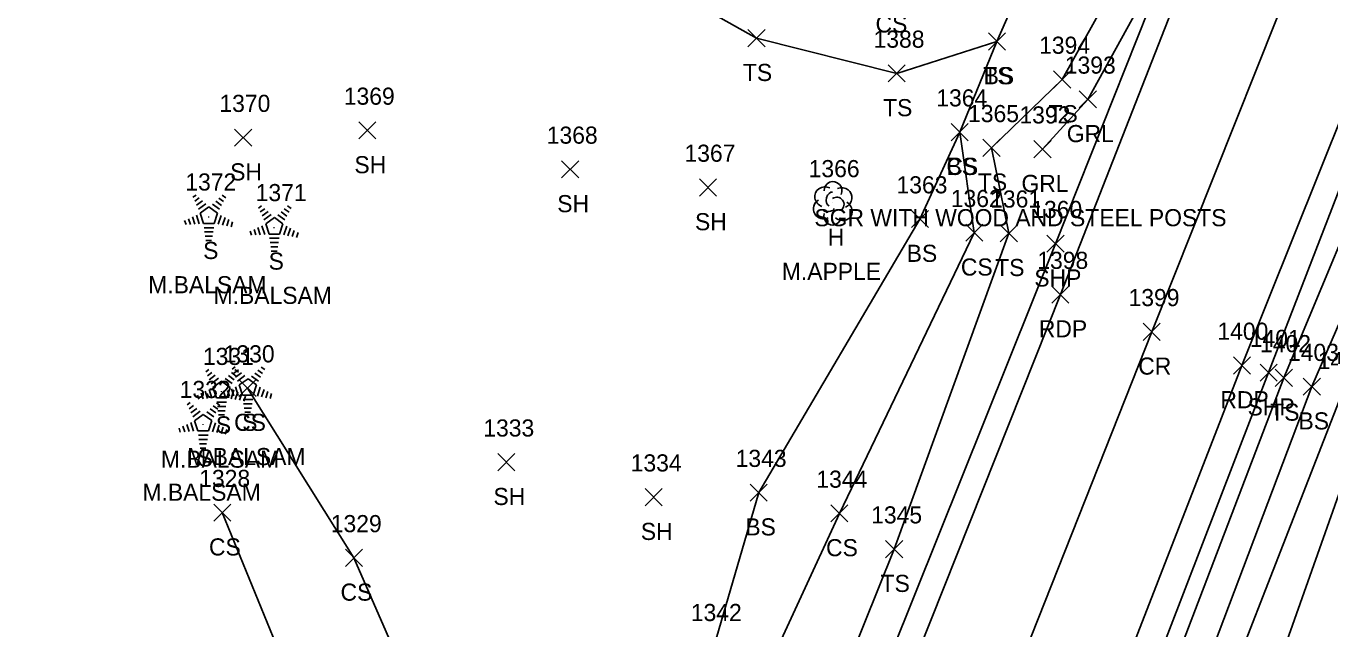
# Model space of a CAD drawing. Extents: x 1554917 to 1555870, y 813367 to 816333.
# Drawn here: x 1555040.5 to 1555192.9, y 813861.5 to 813931.9 of the extents above; entities that cross this region are included whole.
import ezdxf

# ---------------------------------------------------------------- set-up
doc = ezdxf.new("R2010")
doc.units = 0
for name, color, linetype in [('L_A', 7, 'Continuous'), ('L_C', 7, 'Continuous'), ('L_I', 7, 'Continuous'), ('L_TIC', 7, 'Continuous'), ('LELB', 7, 'Continuous'), ('LTC', 7, 'Continuous'), ('LTD', 7, 'Continuous'), ('P_A', 7, 'Continuous'), ('P_I', 7, 'Continuous'), ('P_TIC', 7, 'Continuous'), ('PET', 7, 'Continuous'), ('PRC', 7, 'Continuous'), ('PSP', 7, 'Continuous'), ('R_A', 7, 'Continuous'), ('R_C', 7, 'Continuous'), ('R_I', 7, 'Continuous'), ('R_TIC', 7, 'Continuous'), ('RGR', 7, 'Continuous')]:
    doc.layers.add(name, color=color, linetype=linetype)

msp = doc.modelspace()

# ---------------------------------------------------------------- linework, layer by layer
at = {"layer": 'L_TIC'}
for points in [[(1555124.87, 813929.47), (1555126.87, 813931.47)], [(1555126.87, 813929.47), (1555124.87, 813931.47)], [(1555152.95, 813929.09), (1555154.95, 813931.09)], [(1555154.95, 813929.09), (1555152.95, 813931.09)], [(1555152.95, 813929.09), (1555154.95, 813931.09)], [(1555154.95, 813929.09), (1555152.95, 813931.09)], [(1555141.24, 813925.36), (1555143.24, 813927.36)], [(1555143.24, 813925.36), (1555141.24, 813927.36)], [(1555160.57, 813924.65), (1555162.57, 813926.65)], [(1555162.57, 813924.65), (1555160.57, 813926.65)], [(1555064.9, 813917.86), (1555066.9, 813919.86)], [(1555066.9, 813917.86), (1555064.9, 813919.86)], [(1555079.4, 813918.7), (1555081.4, 813920.7)], [(1555081.4, 813918.7), (1555079.4, 813920.7)], [(1555148.61, 813918.5), (1555150.61, 813920.5)], [(1555150.61, 813918.5), (1555148.61, 813920.5)], [(1555148.61, 813918.5), (1555150.61, 813920.5)], [(1555150.61, 813918.5), (1555148.61, 813920.5)], [(1555152.32, 813916.67), (1555154.32, 813918.67)], [(1555154.32, 813916.67), (1555152.32, 813918.67)], [(1555103.1, 813914.15), (1555105.1, 813916.15)], [(1555105.1, 813914.15), (1555103.1, 813916.15)], [(1555119.19, 813912.04), (1555121.19, 813914.04)], [(1555121.19, 813912.04), (1555119.19, 813914.04)], [(1555143.96, 813908.35), (1555145.96, 813910.35)], [(1555145.96, 813908.35), (1555143.96, 813910.35)], [(1555150.3, 813906.75), (1555152.3, 813908.75)], [(1555152.3, 813906.75), (1555150.3, 813908.75)], [(1555154.34, 813906.69), (1555156.34, 813908.69)], [(1555156.34, 813906.69), (1555154.34, 813908.69)], [(1555186.47, 813889.8), (1555188.47, 813891.8)], [(1555188.47, 813889.8), (1555186.47, 813891.8)], [(1555065.4, 813888.61), (1555067.4, 813890.61)], [(1555067.4, 813888.61), (1555065.4, 813890.61)], [(1555189.74, 813888.78), (1555191.74, 813890.78)], [(1555191.74, 813888.78), (1555189.74, 813890.78)], [(1555095.64, 813879.95), (1555097.64, 813881.95)], [(1555097.64, 813879.95), (1555095.64, 813881.95)], [(1555112.86, 813875.87), (1555114.86, 813877.87)], [(1555114.86, 813875.87), (1555112.86, 813877.87)], [(1555125.12, 813876.4), (1555127.12, 813878.4)], [(1555127.12, 813876.4), (1555125.12, 813878.4)], [(1555062.46, 813874.06), (1555064.46, 813876.06)], [(1555064.46, 813874.06), (1555062.46, 813876.06)], [(1555134.55, 813873.97), (1555136.55, 813875.97)], [(1555136.55, 813873.97), (1555134.55, 813875.97)], [(1555140.95, 813869.8), (1555142.95, 813871.8)], [(1555142.95, 813869.8), (1555140.95, 813871.8)], [(1555077.83, 813868.78), (1555079.83, 813870.78)], [(1555079.83, 813868.78), (1555077.83, 813870.78)]]:
    msp.add_lwpolyline(points, dxfattribs=at)
at = {"layer": 'LELB'}
for points in [[(1555078.74, 813957.64), (1555092.79, 813950.17), (1555112.4, 813938.05), (1555125.87, 813930.47), (1555142.24, 813926.36), (1555153.95, 813930.09)], [(1555019.54, 813585.69), (1555024.77, 813597.99), (1555042.65, 813620.9), (1555048.58, 813631.85), (1555066.52, 813674.6), (1555093.66, 813750.68), (1555103.98, 813778.92), (1555100.94, 813788.26), (1555095.86, 813797.4), (1555100.34, 813804.26), (1555113.07, 813834.65), (1555120.88, 813859.4), (1555126.12, 813877.4), (1555144.96, 813909.35), (1555149.61, 813919.5), (1555153.95, 813930.09), (1555158.29, 813940)], [(1554960.86, 813387.22), (1554975.88, 813430.61), (1554997.67, 813492.71), (1555013.89, 813538.05), (1555028.68, 813579.18), (1555048.82, 813626.54), (1555068.18, 813674.18), (1555096.05, 813749.22), (1555111.01, 813785.1), (1555115.51, 813798.83), (1555119.3, 813812.87), (1555134.87, 813853.17), (1555141.95, 813870.8), (1555155.34, 813907.69), (1555153.32, 813917.67), (1555161.57, 813925.65), (1555168.92, 813938.89)], [(1555091.02, 813589.64), (1555093.93, 813609.08), (1555110.01, 813657.36), (1555123.68, 813699.33), (1555136.3, 813730.66), (1555163.02, 813794.74), (1555179.29, 813835.95), (1555197.25, 813886.69), (1555209.44, 813915.13), (1555210.66, 813920.37)], [(1554992.4, 813377.01), (1555009.62, 813423.34), (1555030.72, 813482.86), (1555047.7, 813528.1), (1555056, 813550.42), (1555062.05, 813566.99), (1555080.33, 813615.57), (1555099.41, 813662.25), (1555114.13, 813700.62), (1555127, 813733.84), (1555152.94, 813799.24), (1555168.16, 813840.25), (1555187.47, 813890.8), (1555199.5, 813919.6)], [(1555111.01, 813785.1), (1555105.42, 813789.67), (1555105.04, 813797.66), (1555119.58, 813831.83), (1555126.62, 813855.57), (1555135.55, 813874.97), (1555151.3, 813907.75), (1555149.61, 813919.5)], [(1554997.34, 813375.96), (1555001.03, 813380.2), (1555008.26, 813399.3), (1555016.85, 813422.36), (1555039.01, 813478.41), (1555055.21, 813525.71), (1555062.73, 813548.53), (1555066.84, 813564.4), (1555085.89, 813613.91), (1555101.8, 813661.36), (1555117.2, 813700.9), (1555129.69, 813732.82), (1555155.55, 813797.61), (1555171.4, 813838.65), (1555190.74, 813889.78), (1555201.42, 813914.42), (1555204.39, 813917.83), (1555206.44, 813916.94)], [(1555060.32, 813524.58), (1555067.83, 813537.87), (1555070.43, 813550.96), (1555072.05, 813560.86), (1555087.88, 813613.15), (1555106.35, 813658.95), (1555120.2, 813700.04), (1555133.19, 813731.1), (1555158.65, 813797.07), (1555174.38, 813837.99), (1555194.21, 813888.82), (1555206.44, 813916.94)], [(1555091.62, 813821.03), (1555091.89, 813839.84), (1555078.83, 813869.78), (1555066.4, 813889.61)], [(1555081.71, 813836.71), (1555072.21, 813853.66), (1555063.46, 813875.06)]]:
    msp.add_lwpolyline(points, dxfattribs=at)
at = {"layer": 'LTC'}
for p, q in [((1555060.03, 813911.89), (1555060.39, 813912.15)), ((1555060.24, 813911.42), (1555060.77, 813911.81)), ((1555060.45, 813910.96), (1555061.15, 813911.47)), ((1555060.66, 813910.49), (1555061.54, 813911.13)), ((1555060.88, 813910.04), (1555061.9, 813910.77)), ((1555061.9, 813910.77), (1555062.89, 813910.05)), ((1555062.32, 813911.08), (1555063.13, 813910.5)), ((1555062.69, 813911.43), (1555063.37, 813910.94)), ((1555063.06, 813911.78), (1555063.61, 813911.38)), ((1555063.43, 813912.13), (1555063.85, 813911.83)), ((1555067.68, 813910.64), (1555068.03, 813910.9)), ((1555071.08, 813910.88), (1555071.49, 813910.58)), ((1555059.06, 813909.17), (1555059.22, 813908.7)), ((1555059.52, 813909.39), (1555059.73, 813908.73)), ((1555059.97, 813909.6), (1555060.25, 813908.77)), ((1555060.43, 813909.82), (1555060.76, 813908.8)), ((1555060.88, 813910.04), (1555061.27, 813908.84)), ((1555062.89, 813910.05), (1555062.5, 813908.84)), ((1555063.33, 813909.78), (1555062.99, 813908.74)), ((1555063.78, 813909.53), (1555063.49, 813908.64)), ((1555064.22, 813909.28), (1555063.98, 813908.55)), ((1555067.89, 813910.18), (1555068.42, 813910.56)), ((1555068.1, 813909.71), (1555068.8, 813910.22)), ((1555068.31, 813909.25), (1555069.18, 813909.88)), ((1555068.53, 813908.79), (1555069.54, 813909.53)), ((1555069.54, 813909.53), (1555070.54, 813908.8)), ((1555069.96, 813909.84), (1555070.77, 813909.25)), ((1555070.33, 813910.19), (1555071.01, 813909.69)), ((1555070.7, 813910.54), (1555071.25, 813910.14)), ((1555062.5, 813908.84), (1555061.27, 813908.84)), ((1555062.46, 813908.34), (1555061.32, 813908.34)), ((1555062.38, 813907.84), (1555061.39, 813907.84)), ((1555064.66, 813909.03), (1555064.48, 813908.45)), ((1555066.71, 813907.92), (1555066.86, 813907.46)), ((1555067.16, 813908.14), (1555067.38, 813907.49)), ((1555067.62, 813908.36), (1555067.89, 813907.52)), ((1555068.08, 813908.57), (1555068.41, 813907.55)), ((1555068.53, 813908.79), (1555068.92, 813907.6)), ((1555070.15, 813907.6), (1555068.92, 813907.6)), ((1555070.54, 813908.8), (1555070.15, 813907.6)), ((1555070.98, 813908.53), (1555070.64, 813907.49)), ((1555071.42, 813908.28), (1555071.13, 813907.4)), ((1555071.87, 813908.03), (1555071.63, 813907.3)), ((1555072.31, 813907.78), (1555072.12, 813907.21)), ((1555062.3, 813907.34), (1555061.46, 813907.34)), ((1555062.21, 813906.84), (1555061.54, 813906.84)), ((1555070.11, 813907.1), (1555068.96, 813907.1)), ((1555070.03, 813906.6), (1555069.04, 813906.6)), ((1555069.94, 813906.1), (1555069.11, 813906.1)), ((1555069.86, 813905.6), (1555069.18, 813905.6)), ((1555061.52, 813891.52), (1555061.87, 813891.78)), ((1555061.73, 813891.05), (1555062.25, 813891.44)), ((1555061.93, 813890.59), (1555062.64, 813891.1)), ((1555064.17, 813891.06), (1555064.85, 813890.57)), ((1555064.54, 813891.41), (1555065.09, 813891.01)), ((1555064.59, 813891.82), (1555064.95, 813892.08)), ((1555064.8, 813891.36), (1555065.33, 813891.74)), ((1555064.91, 813891.76), (1555065.33, 813891.45)), ((1555065.01, 813890.89), (1555065.71, 813891.4)), ((1555065.22, 813890.42), (1555066.1, 813891.06)), ((1555066.88, 813891.02), (1555067.69, 813890.43)), ((1555067.25, 813891.36), (1555067.93, 813890.87)), ((1555067.62, 813891.71), (1555068.17, 813891.31)), ((1555067.99, 813892.06), (1555068.41, 813891.76)), ((1555061.91, 813889.45), (1555062.25, 813888.43)), ((1555062.14, 813890.12), (1555063.02, 813890.76)), ((1555062.37, 813889.67), (1555063.38, 813890.4)), ((1555062.37, 813889.67), (1555062.76, 813888.47)), ((1555063.38, 813890.4), (1555064.38, 813889.68)), ((1555063.8, 813890.71), (1555064.61, 813890.13)), ((1555064.38, 813889.68), (1555063.99, 813888.47)), ((1555064.08, 813889.32), (1555064.29, 813888.66)), ((1555064.82, 813889.41), (1555064.48, 813888.37)), ((1555064.53, 813889.53), (1555064.81, 813888.7)), ((1555064.99, 813889.75), (1555065.32, 813888.73)), ((1555065.44, 813889.97), (1555066.46, 813890.7)), ((1555065.44, 813889.97), (1555065.83, 813888.78)), ((1555066.46, 813890.7), (1555067.45, 813889.98)), ((1555067.45, 813889.98), (1555067.06, 813888.78)), ((1555067.89, 813889.71), (1555067.55, 813888.67)), ((1555068.34, 813889.46), (1555068.05, 813888.57)), ((1555059.37, 813887.65), (1555059.72, 813887.91)), ((1555060.55, 813888.8), (1555060.7, 813888.33)), ((1555061, 813889.01), (1555061.22, 813888.36)), ((1555061.46, 813889.23), (1555061.73, 813888.4)), ((1555063.99, 813888.47), (1555062.76, 813888.47)), ((1555062.77, 813887.89), (1555063.18, 813887.59)), ((1555063.95, 813887.97), (1555062.8, 813887.97)), ((1555063.62, 813889.1), (1555063.78, 813888.63)), ((1555065.26, 813889.16), (1555064.97, 813888.27)), ((1555065.7, 813888.91), (1555065.47, 813888.18)), ((1555067.06, 813888.78), (1555065.83, 813888.78)), ((1555067.02, 813888.28), (1555065.88, 813888.28)), ((1555066.94, 813887.78), (1555065.95, 813887.78)), ((1555066.15, 813888.65), (1555065.96, 813888.08)), ((1555068.78, 813889.21), (1555068.54, 813888.48)), ((1555069.22, 813888.96), (1555069.04, 813888.38)), ((1555059.58, 813887.19), (1555060.11, 813887.57)), ((1555059.79, 813886.72), (1555060.49, 813887.23)), ((1555060, 813886.26), (1555060.87, 813886.9)), ((1555060.22, 813885.8), (1555061.23, 813886.54)), ((1555061.23, 813886.54), (1555062.23, 813885.81)), ((1555061.65, 813886.85), (1555062.46, 813886.26)), ((1555062.02, 813887.2), (1555062.7, 813886.7)), ((1555062.39, 813887.55), (1555062.94, 813887.15)), ((1555063.86, 813887.47), (1555062.88, 813887.47)), ((1555063.78, 813886.97), (1555062.95, 813886.97)), ((1555063.7, 813886.47), (1555063.02, 813886.47)), ((1555066.86, 813887.28), (1555066.02, 813887.28)), ((1555066.77, 813886.78), (1555066.1, 813886.78)), ((1555058.4, 813884.93), (1555058.55, 813884.47)), ((1555058.86, 813885.15), (1555059.07, 813884.5)), ((1555059.31, 813885.37), (1555059.58, 813884.53)), ((1555059.77, 813885.58), (1555060.1, 813884.56)), ((1555060.22, 813885.8), (1555060.61, 813884.61)), ((1555062.23, 813885.81), (1555061.84, 813884.61)), ((1555062.67, 813885.54), (1555062.33, 813884.5)), ((1555063.11, 813885.29), (1555062.82, 813884.41)), ((1555063.56, 813885.04), (1555063.32, 813884.31)), ((1555064, 813884.79), (1555063.81, 813884.22)), ((1555061.84, 813884.61), (1555060.61, 813884.61)), ((1555061.8, 813884.11), (1555060.66, 813884.11)), ((1555061.72, 813883.61), (1555060.73, 813883.61)), ((1555061.63, 813883.11), (1555060.8, 813883.11)), ((1555061.55, 813882.61), (1555060.87, 813882.61))]:
    msp.add_line(p, q, dxfattribs=at)
at = {"layer": 'LTD'}
msp.add_line((1555134.76, 813911.24), (1555134.76, 813911.24), dxfattribs=at)
msp.add_line((1555134.76, 813911.24), (1555134.76, 813911.24), dxfattribs=at)
msp.add_arc((1555134.8, 813912.67), 1.05, 335.5272, 180.9563, dxfattribs=at)
for centre, major_axis, ratio, start_param, end_param in [((1555133.97, 813911.9), (1.21, -0.51), 0.895232, 1.570796, 4.712389), ((1555134.55, 813911.69), (-0.208, -0.792), 0.645439, 3.141593, 6.283185), ((1555135.8, 813911.82), (-1.14, -0.48), 0.949671, 1.570796, 4.712389), ((1555133.67, 813910.53), (0.58, -1.04), 0.959034, 3.141593, 6.283185), ((1555135.26, 813911.07), (-0.5, 0.667), 0.989748, 3.141593, 6.283185), ((1555135.76, 813910.4), (-1.09, 0.79), 0.841452, 1.570796, 4.712389), ((1555134.76, 813909.74), (0.26, 1.06), 0.942809, 1.570796, 4.712389), ((1555134.3, 813910.49), (-0.625, -0.083), 0.423636, 0, 3.141593)]:
    msp.add_ellipse(centre, major_axis=major_axis, ratio=ratio, start_param=start_param, end_param=end_param, dxfattribs=at)
at = {"layer": 'P_TIC'}
for points in [[(1555159.79, 813905.47), (1555161.79, 813907.47)], [(1555161.79, 813905.47), (1555159.79, 813907.47)], [(1555160.36, 813899.53), (1555162.36, 813901.53)], [(1555162.36, 813899.53), (1555160.36, 813901.53)], [(1555171.03, 813895.18), (1555173.03, 813897.18)], [(1555173.03, 813895.18), (1555171.03, 813897.18)], [(1555181.57, 813891.25), (1555183.57, 813893.25)], [(1555183.57, 813891.25), (1555181.57, 813893.25)], [(1555184.69, 813890.41), (1555186.69, 813892.41)], [(1555186.69, 813890.41), (1555184.69, 813892.41)]]:
    msp.add_lwpolyline(points, dxfattribs=at)
at = {"layer": 'PET'}
for points in [[(1554965.43, 813385.56), (1554980.95, 813429.92), (1555003.19, 813490.59), (1555019.55, 813535.73), (1555035.2, 813576.47), (1555053.52, 813624.76), (1555072.33, 813672.52), (1555101.11, 813747.71), (1555125.53, 813809.89), (1555141.72, 813851.12), (1555161.36, 813900.53), (1555183.5, 813956.99)], [(1554987.55, 813378.28), (1555004.34, 813425.43), (1555025.15, 813482.53), (1555042.33, 813529.78), (1555057.09, 813568.35), (1555075.57, 813617.35), (1555093.79, 813663.7), (1555108.49, 813702.81), (1555121.71, 813736.27), (1555147.41, 813801.52), (1555163.02, 813841.94), (1555182.57, 813892.25), (1555203.7, 813945.01)]]:
    msp.add_lwpolyline(points, dxfattribs=at)
at = {"layer": 'PRC'}
msp.add_lwpolyline([(1554976.76, 813382.18), (1554992.84, 813427.9), (1555014.07, 813486.01), (1555030.62, 813532.31), (1555046.37, 813573.08), (1555064.69, 813621.19), (1555082.41, 813667.53), (1555112.1, 813744.1), (1555110.69, 813739.79), (1555136.16, 813805.74), (1555152.52, 813846.93), (1555172.03, 813896.18), (1555193.96, 813951.2), (1555206.37, 813983.4), (1555218.13, 814013.22), (1555228.65, 814039.26), (1555237.93, 814064.31), (1555252.22, 814099.76), (1555265.8, 814135.89), (1555275.26, 814160.09), (1555297.17, 814214.77), (1555313.83, 814257.94), (1555329.72, 814298.26), (1555342.03, 814329.92)], dxfattribs=at)
at = {"layer": 'PSP'}
for points in [[(1554990.52, 813377.71), (1555007.26, 813424.1), (1555027.97, 813481.79), (1555045.41, 813528.93), (1555059.94, 813567), (1555096.82, 813663.08), (1555111.75, 813701.59), (1555124.82, 813734.75), (1555150.26, 813800.36), (1555166.19, 813840.91), (1555185.69, 813891.41), (1555197.67, 813922.42), (1555211.91, 813956.86)], [(1554963, 813386.3), (1554978.53, 813430.4), (1555000.44, 813491.39), (1555017.18, 813537.03), (1555032.55, 813577.93), (1555050.86, 813625.69), (1555069.49, 813673.81), (1555098.21, 813748.28), (1555122.69, 813810.6), (1555138.9, 813851.92), (1555160.79, 813906.47), (1555173.05, 813937.33)]]:
    msp.add_lwpolyline(points, dxfattribs=at)
at = {"layer": 'R_TIC'}
for points in [[(1555163.57, 813922.33), (1555165.57, 813924.33)], [(1555165.57, 813922.33), (1555163.57, 813924.33)], [(1555158.27, 813916.51), (1555160.27, 813918.51)], [(1555160.27, 813916.51), (1555158.27, 813918.51)]]:
    msp.add_lwpolyline(points, dxfattribs=at)
at = {"layer": 'RGR'}
msp.add_lwpolyline([(1555159.27, 813917.51), (1555164.57, 813923.33), (1555172.45, 813937.61), (1555174.85, 813944.62), (1555176.88, 813950.76), (1555185.36, 813973.38), (1555192.77, 813990.92), (1555204.01, 814018.12), (1555214.74, 814044.68), (1555224.38, 814069.2), (1555237.86, 814103.71), (1555245.14, 814124.79), (1555246.27, 814138.04)], dxfattribs=at)

# ---------------------------------------------------------------- texts
at = {"layer": 'L_A'}
for s, p in [('CS', (1555139.77, 813931.14)), ('TS', (1555124.28, 813925.47)), ('TS', (1555152.36, 813925.09)), ('BS', (1555152.39, 813925.09)), ('TS', (1555140.65, 813921.36)), ('TS', (1555159.98, 813920.65)), ('SH', (1555078.89, 813914.7)), ('SH', (1555064.38, 813913.86)), ('CS', (1555148.05, 813914.5)), ('BS', (1555148.05, 813914.5)), ('TS', (1555151.73, 813912.67)), ('SH', (1555102.59, 813910.15)), ('SH', (1555118.68, 813908.04)), ('H', (1555134.19, 813906.24)), ('S', (1555061.22, 813904.68)), ('BS', (1555143.41, 813904.35)), ('S', (1555068.87, 813903.44)), ('CS', (1555149.74, 813902.75)), ('TS', (1555153.75, 813902.69)), ('TS', (1555185.88, 813885.8)), ('S', (1555062.71, 813884.31)), ('CS', (1555064.84, 813884.61)), ('S', (1555065.78, 813884.61)), ('BS', (1555189.18, 813884.78)), ('S', (1555060.56, 813880.45)), ('SH', (1555095.13, 813875.95)), ('BS', (1555124.56, 813872.4)), ('SH', (1555112.35, 813871.87)), ('CS', (1555061.9, 813870.06)), ('CS', (1555133.99, 813869.97)), ('CS', (1555077.27, 813864.78)), ('TS', (1555140.36, 813865.8))]:
    msp.add_text(s, height=2, dxfattribs=at).set_placement(p)
at = {"layer": 'L_C'}
for s, p in [('M.APPLE', (1555128.82, 813902.24)), ('M.BALSAM', (1555054.8, 813900.68)), ('M.BALSAM', (1555062.44, 813899.44)), ('M.BALSAM', (1555056.28, 813880.31)), ('M.BALSAM', (1555059.36, 813880.61)), ('M.BALSAM', (1555054.13, 813876.45))]:
    msp.add_text(s, height=2, dxfattribs=at).set_placement(p)
at = {"layer": 'L_I'}
for s, p in [('1388', (1555139.54, 813929.36)), ('1394', (1555158.88, 813928.65)), ('1369', (1555077.65, 813922.7)), ('1364', (1555146.87, 813922.5)), ('1364', (1555146.87, 813922.5)), ('1370', (1555063.12, 813921.86)), ('1365', (1555150.58, 813920.67)), ('1368', (1555101.36, 813918.15)), ('1367', (1555117.45, 813916.04)), ('1366', (1555131.96, 813914.24)), ('1372', (1555059.14, 813912.68)), ('1363', (1555142.22, 813912.35)), ('1371', (1555067.36, 813911.44)), ('1362', (1555148.56, 813910.75)), ('1361', (1555153.16, 813910.69)), ('1402', (1555184.69, 813893.8)), ('1331', (1555061.19, 813892.31)), ('1330', (1555063.62, 813892.61)), ('1330', (1555063.62, 813892.61)), ('1403', (1555187.96, 813892.78)), ('1404', (1555191.43, 813891.82)), ('1332', (1555058.48, 813888.45)), ('1333', (1555093.95, 813883.95)), ('1334', (1555111.17, 813879.87)), ('1343', (1555123.43, 813880.4)), ('1328', (1555060.76, 813878.06)), ('1344', (1555132.86, 813877.97)), ('1345', (1555139.26, 813873.8)), ('1329', (1555076.13, 813872.78)), ('1342', (1555118.19, 813862.4))]:
    msp.add_text(s, height=2, dxfattribs=at).set_placement(p)
at = {"layer": 'LTC'}
for p in [(1555061.78, 813909.79), (1555069.42, 813908.54), (1555063.26, 813889.41), (1555066.34, 813889.72), (1555061.11, 813885.55)]:
    msp.add_text('.', height=1.04, rotation=270, dxfattribs=at).set_placement(p)
at = {"layer": 'P_A'}
for s, p in [('SHP', (1555158.32, 813901.47)), ('RDP', (1555158.85, 813895.53)), ('CR', (1555170.46, 813891.18)), ('RDP', (1555180.06, 813887.25)), ('SHP', (1555183.23, 813886.41))]:
    msp.add_text(s, height=2, dxfattribs=at).set_placement(p)
at = {"layer": 'P_I'}
for s, p in [('1360', (1555157.96, 813909.47)), ('1398', (1555158.67, 813903.53)), ('1399', (1555169.33, 813899.18)), ('1400', (1555179.71, 813895.25)), ('1401', (1555183.49, 813894.41))]:
    msp.add_text(s, height=2, dxfattribs=at).set_placement(p)
at = {"layer": 'R_A'}
for p in [(1555162.11, 813918.33), (1555156.82, 813912.51)]:
    msp.add_text('GRL', height=2, dxfattribs=at).set_placement(p)
at = {"layer": 'R_C'}
msp.add_text('SGR WITH WOOD AND STEEL POSTS', height=2, dxfattribs=at).set_placement((1555132.63, 813908.51))
at = {"layer": 'R_I'}
for s, p in [('1393', (1555161.88, 813926.33)), ('1392', (1555156.58, 813920.51))]:
    msp.add_text(s, height=2, dxfattribs=at).set_placement(p)

doc.saveas('drawing.dxf')
